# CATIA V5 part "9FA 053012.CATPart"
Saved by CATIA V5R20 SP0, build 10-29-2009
Part number: 9FA 053012
Revision: ANY
Definition: UNKNOWN
Nomenclature: 9FA 053012
Source: Unknown
Bounding box of the stored display mesh (mm): x -2.5 to 2.5, y -6.775 to 5.225, z -2.5 to 2.5
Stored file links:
  C:\Users\Utente\Desktop\IO LAVORO\3D X SITO CF\CUMSA\3D files FA\FA 0530SF\9FA 053012.CATPart

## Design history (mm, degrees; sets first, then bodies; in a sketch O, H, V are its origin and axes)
Set1 "FacciaKO#NONE#1423"
  DatumSurface1 "Sup1423_1"
  DatumCurve1 "Crv1423_1"
  Line1 "PCrv1423_1": stored without definition
  Line2 "PCrv1423_2": stored without definition
Set2
  DatumSurface2 "NONE"
Body1 (main body)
